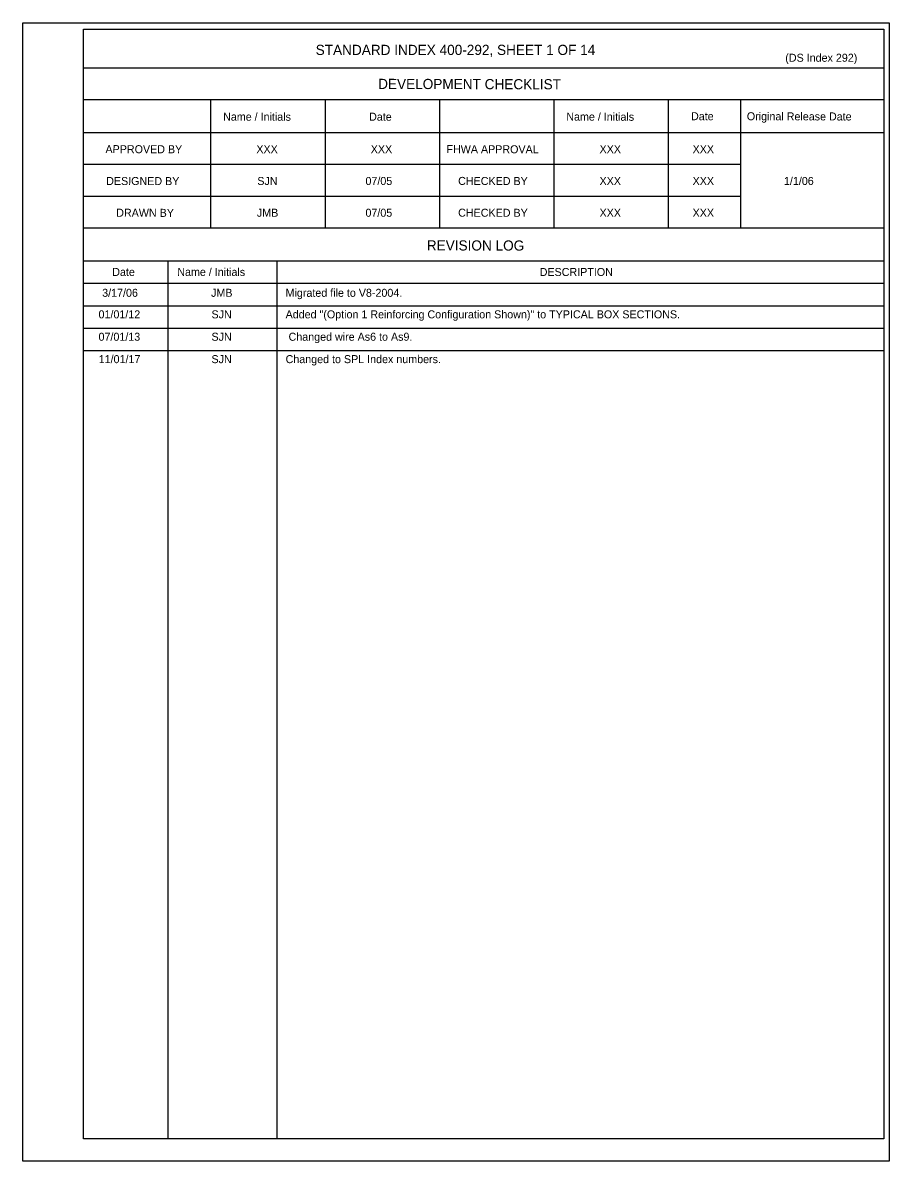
# Model space of a CAD drawing. Extents: x 10340.6 to 10393.7, y 76398.7 to 76426.2.
# Drawn here: x 10377.31 to 10393.67, y 76403.42 to 76424.92 of the extents above; entities that cross this region are included whole.
import ezdxf

# ---------------------------------------------------------------- set-up
doc = ezdxf.new("R2010")
doc.units = 0
for name, color, linetype in [('Border', 7, 'Continuous'), ('Patterning', 7, 'Continuous'), ('SheetBorder_dp', 7, 'Continuous')]:
    doc.layers.add(name, color=color, linetype=linetype)

msp = doc.modelspace()

# ---------------------------------------------------------------- linework, layer by layer
at = {"layer": 'Border'}
for p, q in [((10393.566, 76424.059), (10378.455, 76424.059)), ((10393.566, 76423.459), (10378.455, 76423.459)), ((10380.855, 76423.459), (10380.855, 76421.038)), ((10383.015, 76423.459), (10383.015, 76421.038)), ((10385.175, 76423.459), (10385.175, 76421.038)), ((10387.335, 76423.459), (10387.335, 76421.038)), ((10389.495, 76423.459), (10389.495, 76421.038)), ((10390.857, 76423.459), (10390.857, 76421.038)), ((10393.566, 76422.838), (10378.455, 76422.838)), ((10390.857, 76422.238), (10378.455, 76422.238)), ((10390.857, 76421.638), (10378.455, 76421.638)), ((10393.566, 76421.038), (10378.455, 76421.038)), ((10393.566, 76420.417), (10378.455, 76420.417)), ((10380.046, 76420.417), (10380.046, 76403.837)), ((10382.102, 76420.417), (10382.102, 76403.837)), ((10393.566, 76419.994), (10378.455, 76419.994))]:
    msp.add_line(p, q, dxfattribs=at)
msp.add_lwpolyline([(10378.456, 76424.794), (10393.566, 76424.794), (10393.566, 76403.837), (10378.456, 76403.837)], close=True, dxfattribs=at)
at = {"layer": 'Patterning'}
for p, q in [((10378.455, 76419.571), (10393.566, 76419.571)), ((10378.455, 76419.149), (10393.566, 76419.149)), ((10378.455, 76418.726), (10393.566, 76418.726))]:
    msp.add_line(p, q, dxfattribs=at)
at = {"layer": 'SheetBorder_dp'}
msp.add_line((10377.308, 76403.416), (10377.308, 76403.416), dxfattribs=at)
msp.add_lwpolyline([(10377.308, 76424.916), (10393.668, 76424.916), (10393.668, 76403.416), (10377.308, 76403.416)], close=True, dxfattribs=at)

# ---------------------------------------------------------------- texts
at = {"layer": 'Patterning'}
for s, height, p in [('STANDARD INDEX 400-292, SHEET 1 OF 14', 0.192, (10382.838, 76424.308)), ('(DS Index 292)', 0.1512, (10391.705, 76424.18)), ('XXX', 0.1512, (10381.718, 76422.453)), ('XXX', 0.1512, (10383.878, 76422.453)), ('XXX', 0.1512, (10388.198, 76422.453)), ('XXX', 0.1512, (10389.955, 76422.453)), ('SJN', 0.1512, (10381.736, 76421.853)), ('07/05', 0.1512, (10383.778, 76421.853)), ('XXX', 0.1512, (10388.198, 76421.853)), ('XXX', 0.1512, (10389.955, 76421.853)), ('1/1/06', 0.1512, (10391.68, 76421.853)), ('JMB', 0.1512, (10381.728, 76421.253)), ('07/05', 0.1512, (10383.778, 76421.253)), ('XXX', 0.1512, (10388.198, 76421.253)), ('XXX', 0.1512, (10389.955, 76421.253)), ('DESCRIPTION', 0.1512, (10387.068, 76420.134)), ('3/17/06', 0.1512, (10378.807, 76419.741)), ('JMB', 0.1512, (10380.863, 76419.741)), ('Migrated file to V8-2004.', 0.1512, (10382.27, 76419.741)), ('01/01/12', 0.1512, (10378.738, 76419.334)), ('SJN', 0.1512, (10380.871, 76419.334)), ('Added "(Option 1 Reinforcing Configuration Shown)" to TYPICAL BOX SECTIONS.', 0.1512, (10382.27, 76419.334)), ('07/01/13', 0.1512, (10378.738, 76418.911)), ('SJN', 0.1512, (10380.871, 76418.911)), (' Changed wire As6 to As9.', 0.1512, (10382.27, 76418.911)), ('11/01/17', 0.1512, (10378.741, 76418.488)), ('SJN', 0.1512, (10380.871, 76418.488)), ('Changed to SPL Index numbers.', 0.1512, (10382.27, 76418.488))]:
    msp.add_text(s, height=height, dxfattribs=at).set_placement(p)
for s, height, p in [('DEVELOPMENT CHECKLIST', 0.192, (10384.017, 76423.666)), ('Name / Initials', 0.1512, (10381.09, 76423.068)), ('Date', 0.1512, (10383.846, 76423.067)), ('Name / Initials', 0.1512, (10387.57, 76423.068)), ('Date', 0.1512, (10389.925, 76423.076)), ('Original Release Date', 0.1512, (10390.979, 76423.075)), ('APPROVED BY', 0.1512, (10378.869, 76422.454)), ('FHWA APPROVAL', 0.1512, (10385.307, 76422.454)), ('DESIGNED BY', 0.1512, (10378.882, 76421.853)), ('CHECKED BY', 0.1512, (10385.528, 76421.854)), ('DRAWN BY', 0.1512, (10379.072, 76421.253)), ('CHECKED BY', 0.1512, (10385.528, 76421.254)), ('REVISION LOG', 0.192, (10384.936, 76420.617)), ('Date', 0.1512, (10378.997, 76420.135)), ('Name / Initials', 0.1512, (10380.225, 76420.136))]:
    msp.add_text(s, height=height, rotation=359.8756, dxfattribs=at).set_placement(p)

doc.saveas('drawing.dxf')
